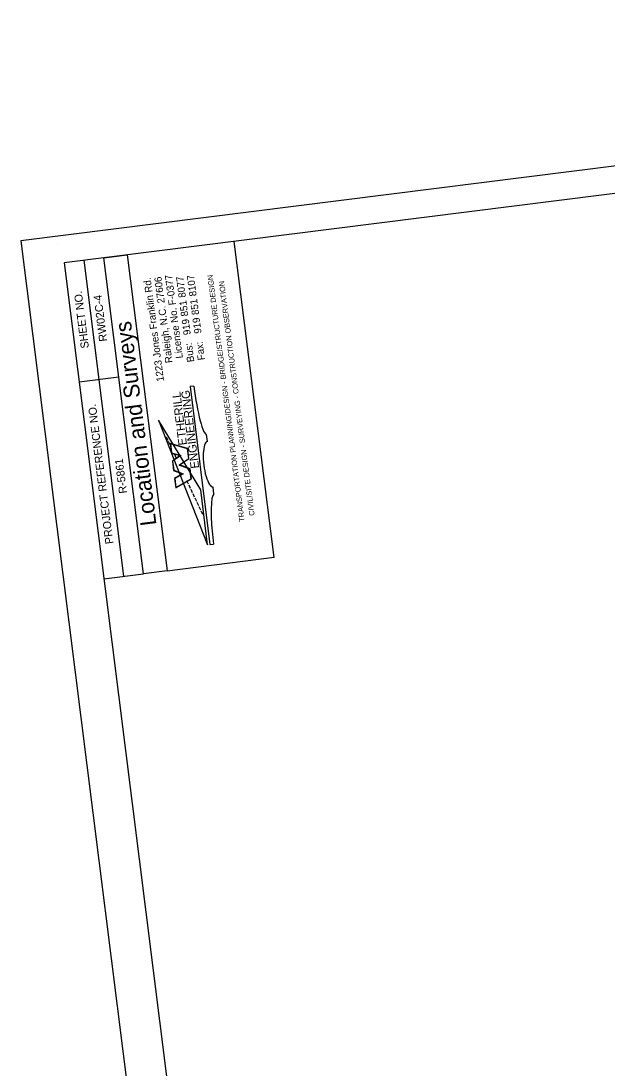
# Model space of a CAD drawing. Extents: x 476627 to 479509, y 495837 to 499842.
# Drawn here: x 476627 to 477437, y 498393 to 499842 of the extents above; entities that cross this region are included whole.
import ezdxf

# ---------------------------------------------------------------- set-up
doc = ezdxf.new("R2010")
doc.units = 0
for name, color, linetype in [('CTL Sheet Border CELL', 7, 'Continuous'), ('CTL Sheet Notes CELL', 7, 'Continuous'), ('Sheet Plot Border Outside CELL', 7, 'Continuous')]:
    doc.layers.add(name, color=color, linetype=linetype)

msp = doc.modelspace()

# ---------------------------------------------------------------- linework, layer by layer
at = {"layer": 'CTL Sheet Border CELL'}
for p, q in [((476626.7, 499537.6), (476626.7, 499537.6)), ((476976.9, 499099.6), (476921.8, 499536.7)), ((476677.2, 499533.9), (476677.2, 499533.9)), ((476677.2, 499533.9), (476677.2, 499533.9)), ((476768.9, 499073.5), (476713.9, 499510.6)), ((476707.1, 499342.3), (476762, 499349.3)), ((476828.7, 499081), (476976.9, 499099.7)), ((476741.4, 499070), (476796.3, 499076.9))]:
    msp.add_line(p, q, dxfattribs=at)
for points in [[(476686.3, 499507.1), (477101.1, 496211.1), (479408.3, 496501.4), (478993.5, 499797.5)], [(476796.3, 499076.9), (476741.3, 499514), (476773.7, 499518.1), (476828.7, 499081)]]:
    msp.add_lwpolyline(points, close=True, dxfattribs=at)
at = {"layer": 'CTL Sheet Notes CELL'}
for p, q in [((476865.9, 499336.4), (476860.9, 499335.8)), ((476860.9, 499335.8), (476888.1, 499117.4)), ((476830.2, 499261.4), (476828, 499266)), ((476833, 499255.4), (476830.9, 499259.9)), ((476884.6, 499259.8), (476883.4, 499269.7)), ((476833.1, 499257), (476834.7, 499243.9)), ((476857, 499249.8), (476833.5, 499256.6)), ((476833.5, 499256.6), (476835.1, 499244.2)), ((476858.7, 499236.6), (476857, 499249.8)), ((476859, 499236.5), (476857.3, 499250.1)), ((476834.7, 499243.9), (476847, 499240.4)), ((476835.1, 499244.2), (476847.8, 499240.5)), ((476847, 499240.4), (476836.1, 499232.8)), ((476836.1, 499232.8), (476837.7, 499220)), ((476847.8, 499240.5), (476836.5, 499232.6)), ((476836.5, 499232.6), (476838, 499220.2)), ((476841.5, 499237.3), (476839.4, 499241.8)), ((476845.5, 499227.4), (476858.7, 499236.6)), ((476846.2, 499227.5), (476859, 499236.5)), ((476837.7, 499220), (476850.2, 499215.2)), ((476838, 499220.2), (476851, 499215.3)), ((476860.5, 499221.7), (476845.5, 499227.4)), ((476860.8, 499222), (476846.2, 499227.5)), ((476862.2, 499208.5), (476860.5, 499221.7)), ((476862.5, 499208.3), (476860.8, 499222)), ((476850.2, 499215.2), (476839.1, 499208.8)), ((476839.1, 499208.8), (476840.8, 499195.7)), ((476851, 499215.3), (476839.5, 499208.6)), ((476839.5, 499208.6), (476841, 499196.2)), ((476840.8, 499195.7), (476862.5, 499208.3)), ((476841, 499196.2), (476862.2, 499208.5)), ((476858.5, 499201.1), (476856.3, 499205.6)), ((476861.3, 499195), (476859.2, 499199.6)), ((476864.1, 499189), (476862, 499193.5)), ((476866.9, 499183), (476864.8, 499187.5)), ((476893.7, 499187), (476892.5, 499196.9)), ((476869.8, 499176.9), (476867.7, 499181.5)), ((476872.6, 499170.9), (476870.5, 499175.4)), ((476875.4, 499164.9), (476873.3, 499169.4)), ((476878.3, 499158.8), (476876.1, 499163.4)), ((476888.1, 499117.4), (476893, 499118.1))]:
    msp.add_line(p, q, dxfattribs=at)
msp.add_lwpolyline([(476884.8, 499117), (476875.3, 499193.1), (476817.1, 499289.4)], close=True, dxfattribs=at)
msp.add_lwpolyline([(476857.3, 499250.1), (476856.9, 499250.2), (476833.1, 499257)], dxfattribs=at)
for centre, major_axis, ratio, start_param, end_param in [((476875, 499337.5), (-8.4, 67.8), 0.134146, 1.570796, 3.141593), ((476888.6, 499228.4), (-3.9, 31.4), 0.289474, 0, 3.141593), ((476902.1, 499119.2), (8.4, -67.8), 0.134146, 3.141593, 4.712389)]:
    msp.add_ellipse(centre, major_axis=major_axis, ratio=ratio, start_param=start_param, end_param=end_param, dxfattribs=at)
at = {"layer": 'Sheet Plot Border Outside CELL'}
msp.add_lwpolyline([(479509.4, 496141.4), (479043.7, 499841.7), (476626.7, 499537.6), (477092.3, 495837.2)], close=True, dxfattribs=at)

# ---------------------------------------------------------------- texts
at = {"layer": 'CTL Sheet Border CELL'}
for s, height, p in [('SHEET NO.', 11.07, (476720.7, 499389.4)), ('RW02C-4', 11.07, (476746, 499398.9)), ('Location and Surveys', 22.147, (476814.2, 499144.7)), ('PROJECT REFERENCE NO.', 11.074, (476754.6, 499118.8)), ('R-5861', 11.07, (476773.4, 499188.7))]:
    msp.add_text(s, height=height, rotation=97.1725, dxfattribs=at).set_placement(p)
at = {"layer": 'CTL Sheet Notes CELL'}
for s, height, rotation, p in [('1223 Jones Franklin Rd. ', 10, 97.4175, (476824.6, 499343.5)), ('Raleigh, N.C. 27606', 10, 97.4175, (476836.4, 499369.1)), ('License No. F-0377', 10, 97.4175, (476850.7, 499375.4)), ('Bus:   919 851 8077', 10, 97.4175, (476866.5, 499370.3)), ('Fax:   919 851 8107', 10, 97.4175, (476881.3, 499373)), ('TRANSPORTATION PLANNING/DESIGN - BRIDGE/STRUCTURE DESIGN', 7.333, 97.4175, (476936.2, 499149.5)), ('CIVIL/SITE DESIGN - SURVEYING - CONSTRUCTION OBSERVATION', 7.333, 97.4175, (476949.9, 499157.7)), ('ETHERILL', 11.67, 97.0911, (476856.3, 499255.4)), ('ENGINEERING', 11.667, 97.0911, (476873.2, 499223.3))]:
    msp.add_text(s, height=height, rotation=rotation, dxfattribs=at).set_placement(p)

doc.saveas('drawing.dxf')
